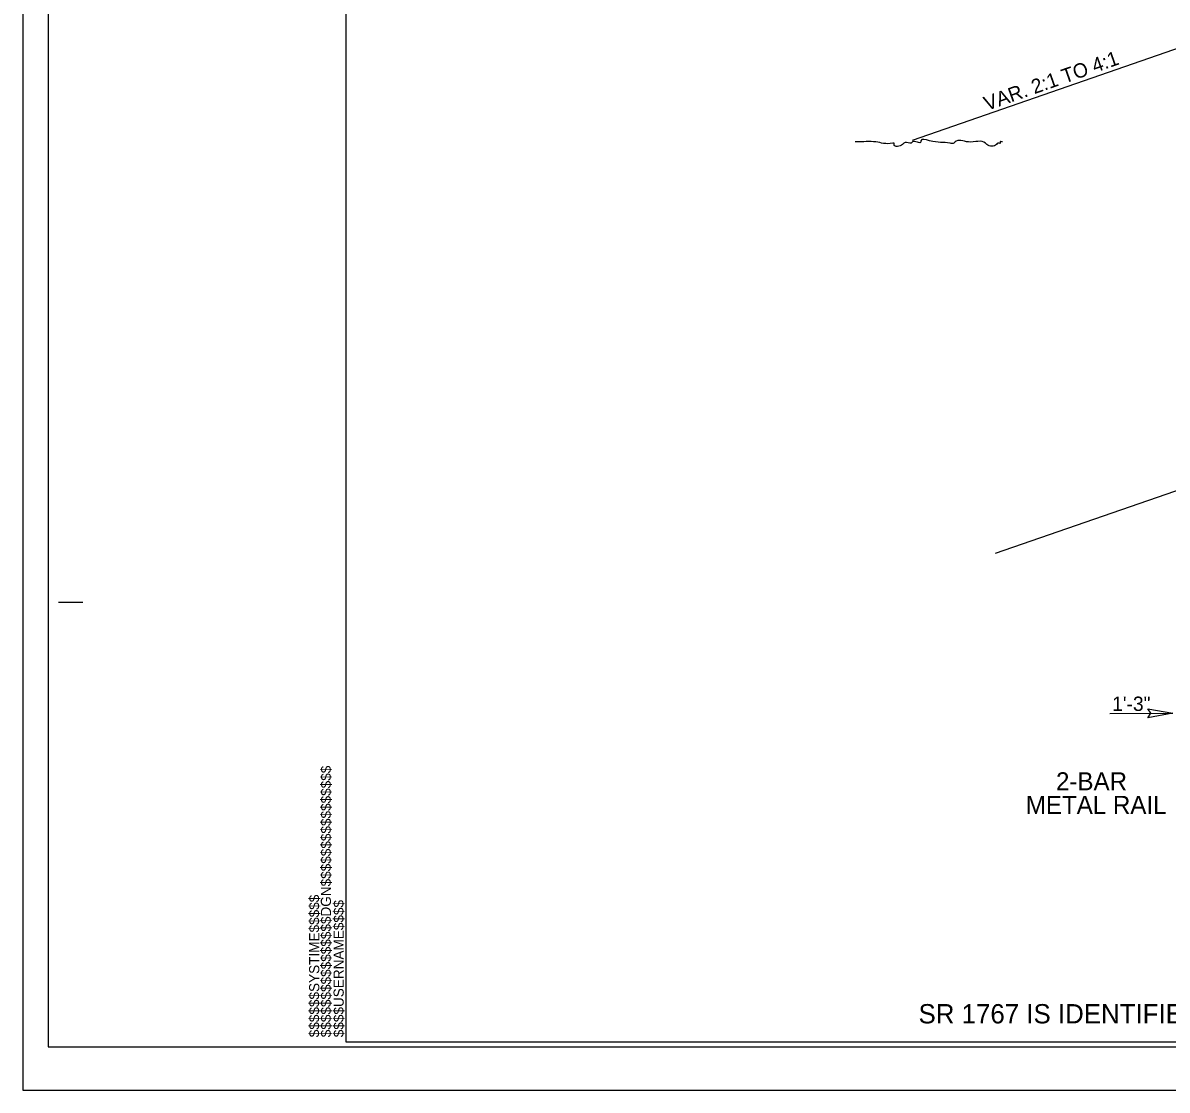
# Model space of a CAD drawing. Extents: x 55823 to 57507, y 47399 to 48499.
# Drawn here: x 55823 to 56415, y 47399 to 47952 of the extents above; entities that cross this region are included whole.
import ezdxf

# ---------------------------------------------------------------- set-up
doc = ezdxf.new("R2010")
doc.units = 0
for name, color, linetype in [('Old_Level_1', 7, 'Continuous'), ('Old_Level_28', 7, 'Continuous'), ('Old_Level_3', 7, 'Continuous'), ('Sheet Plot Border Inside CELL', 7, 'Continuous'), ('Sheet Plot Border Outside CELL', 7, 'Continuous'), ('Sheet Typical CELL', 7, 'Continuous'), ('Typical Text General CELL', 7, 'Continuous')]:
    doc.layers.add(name, color=color, linetype=linetype)

msp = doc.modelspace()

# ---------------------------------------------------------------- linework, layer by layer
at = {"layer": 'Old_Level_1'}
for p, q in [((56426.62, 47940.74), (56283.03, 47890.79)), ((56469.67, 47727), (56326.08, 47677.05))]:
    msp.add_line(p, q, dxfattribs=at)
at = {"layer": 'Old_Level_28'}
msp.add_line((56385.38, 47594.37), (56417.91, 47594.41), dxfattribs=at)
msp.add_lwpolyline([(56404.98, 47596.64), (56417.91, 47594.41), (56404.9, 47592.11), (56406.56, 47594.41)], close=True, dxfattribs=at)
at = {"layer": 'Old_Level_3'}
msp.add_spline([(56329.85, 47890.1), (56328.59, 47890.1), (56328.59, 47889.47), (56327.33, 47889.47), (56326.7, 47888.84), (56321.65, 47888.84), (56321.02, 47889.47), (56312.19, 47890.1), (56305.26, 47890.1), (56304.63, 47889.47), (56302.74, 47889.47), (56292.02, 47890.73), (56287.61, 47890.73), (56287.61, 47890.1), (56283.19, 47890.1), (56282.56, 47889.47), (56281.93, 47889.47), (56278.78, 47889.47), (56278.15, 47888.84), (56273.74, 47888.84), (56273.74, 47889.47), (56273.1, 47889.47), (56264.28, 47890.1), (56254.19, 47890.1), (56253.56, 47890.1)], degree=3, dxfattribs=at)
at = {"layer": 'Sheet Plot Border Inside CELL'}
msp.add_lwpolyline([(57502.66, 48476.93), (55836.16, 48476.93), (55836.16, 47421.83), (57502.66, 47421.83)], close=True, dxfattribs=at)
at = {"layer": 'Sheet Plot Border Outside CELL'}
msp.add_lwpolyline([(57507.16, 48499.38), (55823.16, 48499.38), (55823.16, 47399.38), (57507.16, 47399.38)], close=True, dxfattribs=at)
at = {"layer": 'Sheet Typical CELL'}
for p, q in [((55841.66, 47651.88), (55854.16, 47651.88)), ((55990.16, 47424.38), (55990.16, 47424.38)), ((55990.16, 47424.38), (55990.16, 47424.38)), ((55990.16, 47424.38), (55990.16, 47424.38)), ((55990.16, 47424.38), (55990.16, 47424.38)), ((55990.16, 47424.38), (55990.16, 47424.38)), ((55990.16, 47424.38), (55990.16, 47424.38))]:
    msp.add_line(p, q, dxfattribs=at)
msp.add_lwpolyline([(57490.16, 48474.38), (55990.16, 48474.38), (55990.16, 47424.38), (57490.16, 47424.38)], close=True, dxfattribs=at)
msp.add_lwpolyline([(56027.66, 47424.38), (56027.66, 47424.38)], dxfattribs=at)

# ---------------------------------------------------------------- texts
at = {"layer": 'Old_Level_1'}
msp.add_text('VAR. 2:1 TO 4:1', height=7.4468, rotation=19.40484, dxfattribs=at).set_placement((56321.73, 47906.15))
at = {"layer": 'Old_Level_28'}
for s, height, p in [('1\'-3"', 7.447, (56386.5, 47595.62)), ('SR 1767 IS IDENTIFIED AS A BIKE ROUTE IN THE PIEDMONT TRIAD REGIONAL BIKE STUDY (2005).', 10, (56286.37, 47433.91))]:
    msp.add_text(s, height=height, dxfattribs=at).set_placement(p)
at = {"layer": 'Sheet Typical CELL'}
for s, p in [('$$$$$$$$$$$$$$$$DGN$$$$$$$$$$$$$$$$', (55982.51, 47426.75)), ('$$$$$$SYSTIME$$$$$', (55976.46, 47426.75)), ('$$$$USERNAME$$$$', (55989.09, 47426.76))]:
    msp.add_text(s, height=5.25, rotation=90, dxfattribs=at).set_placement(p)
at = {"layer": 'Typical Text General CELL'}
for s, p in [('2-BAR', (56357.48, 47554.57)), ('METAL RAIL', (56341.87, 47542.35))]:
    msp.add_text(s, height=9.326, rotation=0.00001, dxfattribs=at).set_placement(p)

doc.saveas('drawing.dxf')
